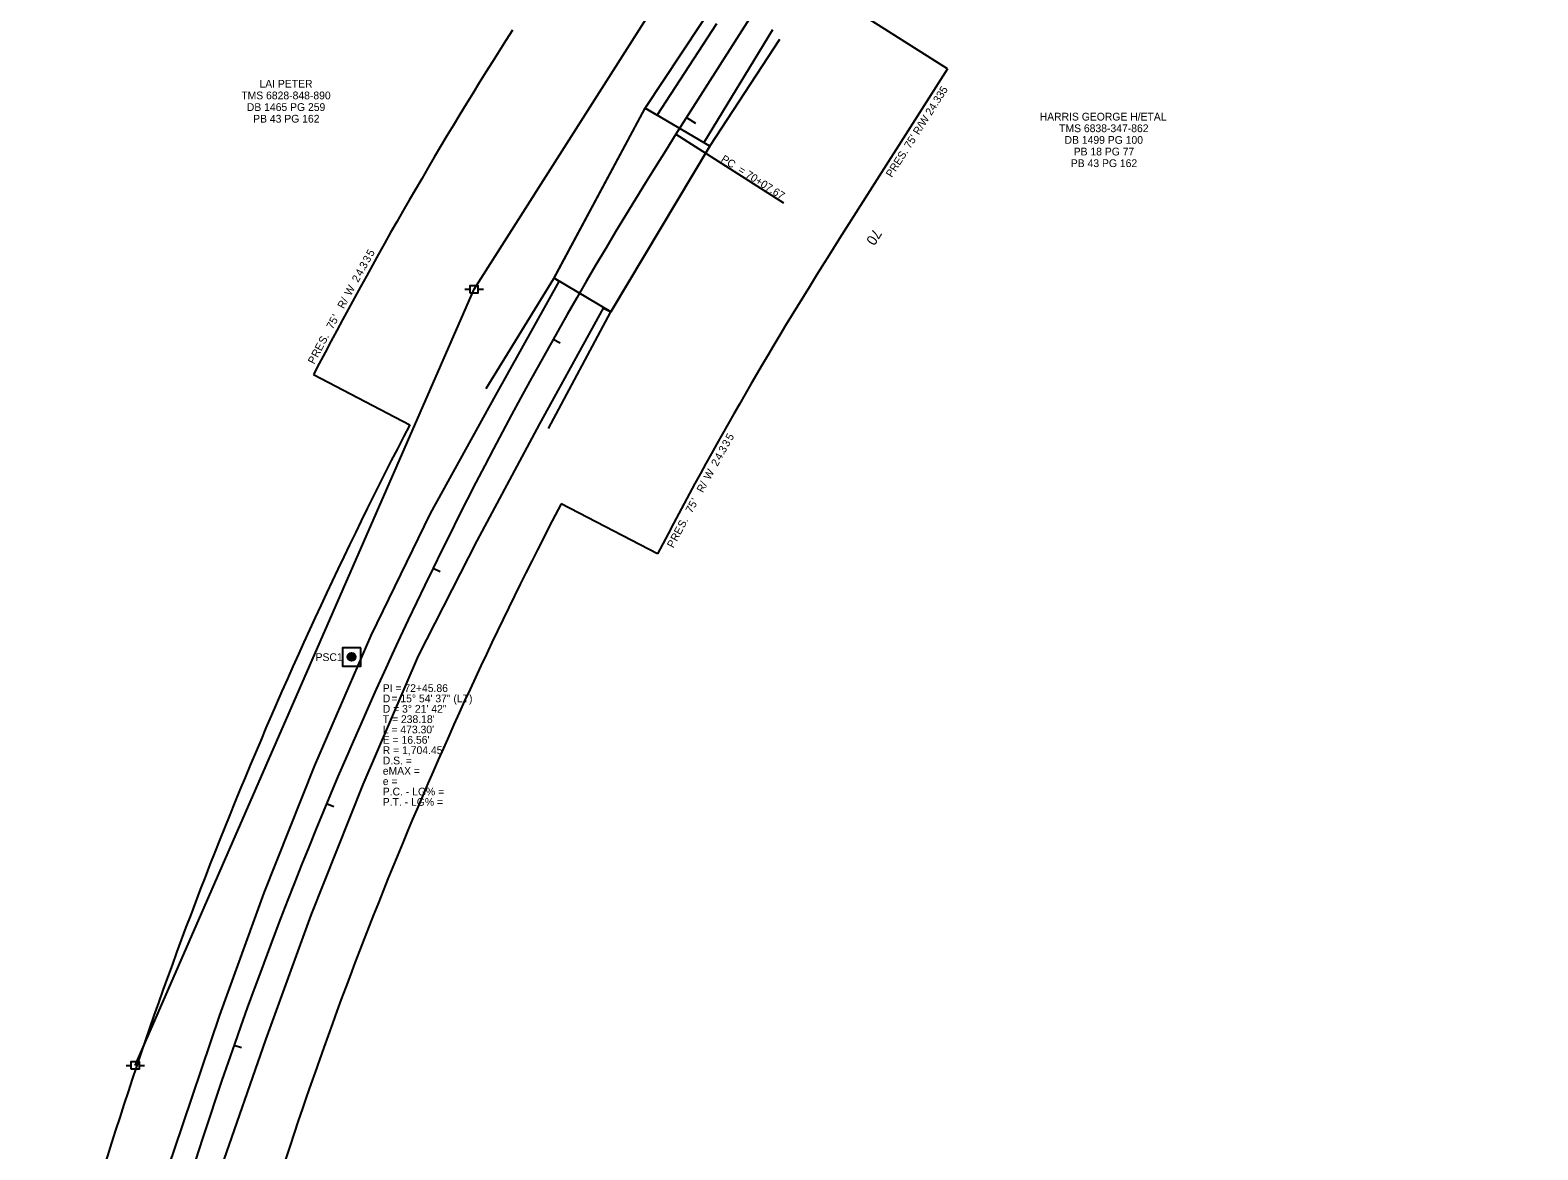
# Model space of a CAD drawing. Extents: x 1628604 to 1635417, y 886385 to 890338.
# Drawn here: x 1631062 to 1631645, y 888076 to 888509 of the extents above; entities that cross this region are included whole.
import ezdxf

# ---------------------------------------------------------------- set-up
doc = ezdxf.new("R2010")
doc.units = 0
for name, color, linetype in [('RD_EX_Bridge', 7, 'Continuous'), ('RD_EX_DV_TX_Prop', 7, 'Continuous'), ('RD_EX_GuardRail', 7, 'Continuous'), ('RD_EX_Road', 7, 'Continuous'), ('RD_EX_RW', 7, 'Continuous'), ('RD_EX_RW_TX', 7, 'Continuous'), ('RD_EX_SU_Pole', 7, 'Continuous'), ('RD_EX_UT', 7, 'Continuous'), ('RD_HC_Cl', 7, 'Continuous'), ('RD_HC_Data', 7, 'Continuous'), ('RD_HC_Data_Tic', 7, 'Continuous'), ('RD_HC_Survey', 7, 'Continuous'), ('RD_HC_Survey_txCode', 7, 'Continuous'), ('RD_HC_TX_Sta20', 7, 'Continuous'), ('SV_Plan_Bridge', 7, 'Continuous')]:
    doc.layers.add(name, color=color, linetype=linetype)

msp = doc.modelspace()

# ---------------------------------------------------------------- linework, layer by layer
at = {"layer": 'RD_EX_Bridge'}
for p, q in [((1631264.25, 888413), (1631299.43, 888478.7)), ((1631324.47, 888464.12), (1631299.43, 888478.7)), ((1631324.47, 888464.12), (1631286.15, 888399.98)), ((1631286.15, 888399.98), (1631264.25, 888413))]:
    msp.add_line(p, q, dxfattribs=at)
at = {"layer": 'RD_EX_GuardRail'}
for points in [[(1631237.99, 888370.31), (1631264.09, 888412.85), (1631299.43, 888478.7), (1631328.07, 888522.09)], [(1631262.14, 888354.83), (1631286.15, 888399.98), (1631324.47, 888464.12), (1631351.54, 888505.46)]]:
    msp.add_lwpolyline(points, dxfattribs=at)
at = {"layer": 'RD_EX_Road'}
for points in [[(1631061.65, 887886.91), (1631073.86, 887933.34), (1631087.39, 887979.64), (1631091.12, 887991.9), (1631101.62, 888029.8), (1631117.32, 888075.69), (1631134.95, 888128.02), (1631152.2, 888175.32), (1631171.74, 888224.62), (1631193.53, 888274.89), (1631216.42, 888321.99), (1631241.71, 888367.79), (1631266.25, 888411.67), (1631264.25, 888413), (1631299.43, 888478.7), (1631304.13, 888476.05), (1631327.2, 888511.47)], [(1631080.06, 887879.92), (1631092.71, 887925.82), (1631106.29, 887972.84), (1631120.8, 888022.75), (1631135.69, 888069.29), (1631152.84, 888118.51), (1631170.28, 888166.75), (1631190.48, 888217.25), (1631211.83, 888266.99), (1631234.52, 888311.47), (1631258.75, 888356.69), (1631283.38, 888401.46), (1631286.15, 888399.98), (1631324.47, 888464.12), (1631322.12, 888465.29), (1631348.79, 888509.12)]]:
    msp.add_lwpolyline(points, dxfattribs=at)
at = {"layer": 'RD_EX_RW'}
for p, q in [((1631416.35, 888493.91), (1631380.92, 888516.46)), ((1631416.35, 888493.91), (1631374.64, 888428.38)), ((1631171.2, 888375.72), (1631208.45, 888356.31)), ((1631304.22, 888306.41), (1631266.98, 888325.81))]:
    msp.add_line(p, q, dxfattribs=at)
for radius, start, end in [(1779.45, 147.5244, 152.47845), (1629.45, 147.5244, 152.47845), (1737.45, 152.47845, 163.43457), (1671.45, 152.47845, 163.43457)]:
    msp.add_arc((1632749.28, 887553.47), radius, start, end, dxfattribs=at)
at = {"layer": 'RD_EX_SU_Pole'}
for p, q in [((1631229.75, 888408.71), (1631231.81, 888408.71)), ((1631233.31, 888408.75), (1631233.31, 888408.75)), ((1631234.81, 888408.71), (1631236.95, 888408.71)), ((1631098.71, 888108.55), (1631100.77, 888108.55)), ((1631102.27, 888108.59), (1631102.27, 888108.59)), ((1631103.77, 888108.55), (1631105.91, 888108.55))]:
    msp.add_line(p, q, dxfattribs=at)
for points in [[(1631231.81, 888407.25), (1631231.81, 888410.25), (1631234.81, 888410.25), (1631234.81, 888407.25)], [(1631100.77, 888107.09), (1631100.77, 888110.09), (1631103.77, 888110.09), (1631103.77, 888107.09)]]:
    msp.add_lwpolyline(points, close=True, dxfattribs=at)
at = {"layer": 'RD_EX_UT'}
msp.add_lwpolyline([(1631102.27, 888108.59), (1631233.31, 888408.75), (1631462.97, 888769.93), (1631644.65, 888948.73)], dxfattribs=at)
at = {"layer": 'RD_HC_Cl'}
msp.add_line((1631589.45, 888905.57), (1631311.37, 888468.65), dxfattribs=at)
msp.add_arc((1632749.28, 887553.47), 1704.45, 147.5244, 163.43457, dxfattribs=at)
at = {"layer": 'RD_HC_Data'}
msp.add_line((1631311.37, 888468.65), (1631352.94, 888442.2), dxfattribs=at)
at = {"layer": 'RD_HC_Data_Tic'}
for p, q in [((1631315.49, 888475.13), (1631318.87, 888472.98)), ((1631263.93, 888389.46), (1631266.55, 888387.99)), ((1631217.47, 888300.93), (1631220.16, 888299.61)), ((1631176.28, 888209.82), (1631179.04, 888208.67)), ((1631140.5, 888116.46), (1631143.33, 888115.47))]:
    msp.add_line(p, q, dxfattribs=at)
at = {"layer": 'RD_HC_Survey'}
for p, q in [((1631184.45, 888266.22), (1631184.45, 888266.94)), ((1631184.5, 888266.05), (1631184.5, 888267.11)), ((1631184.55, 888265.93), (1631184.55, 888267.23)), ((1631184.6, 888265.83), (1631184.6, 888267.33)), ((1631184.65, 888265.75), (1631184.65, 888267.41)), ((1631184.7, 888265.67), (1631184.7, 888267.49)), ((1631184.75, 888265.61), (1631184.75, 888267.55)), ((1631184.8, 888265.55), (1631184.8, 888267.61)), ((1631184.85, 888265.49), (1631184.85, 888267.67)), ((1631184.9, 888265.44), (1631184.9, 888267.72)), ((1631184.95, 888265.4), (1631184.95, 888267.76)), ((1631185, 888265.36), (1631185, 888267.8)), ((1631185.05, 888265.32), (1631185.05, 888267.84)), ((1631185.1, 888265.29), (1631185.1, 888267.87)), ((1631185.15, 888265.25), (1631185.15, 888267.91)), ((1631185.2, 888265.22), (1631185.2, 888267.94)), ((1631185.25, 888265.2), (1631185.25, 888267.96)), ((1631185.3, 888265.17), (1631185.3, 888267.99)), ((1631185.35, 888265.15), (1631185.35, 888268.01)), ((1631185.4, 888265.13), (1631185.4, 888268.03)), ((1631185.45, 888265.11), (1631185.45, 888268.05)), ((1631185.5, 888265.1), (1631185.5, 888268.06)), ((1631185.55, 888265.08), (1631185.55, 888268.08)), ((1631185.6, 888265.07), (1631185.6, 888268.09)), ((1631185.65, 888265.06), (1631185.65, 888268.1)), ((1631185.7, 888265.05), (1631185.7, 888268.11)), ((1631185.75, 888265.04), (1631185.75, 888268.12)), ((1631185.8, 888265.03), (1631185.8, 888268.13)), ((1631185.85, 888265.03), (1631185.85, 888268.13)), ((1631185.9, 888265.03), (1631185.9, 888268.13)), ((1631185.95, 888265.03), (1631185.95, 888268.13)), ((1631186, 888265.03), (1631186, 888268.13)), ((1631186.05, 888265.03), (1631186.05, 888268.13)), ((1631186.1, 888265.03), (1631186.1, 888268.13)), ((1631186.15, 888265.04), (1631186.15, 888268.12)), ((1631186.2, 888265.04), (1631186.2, 888268.12)), ((1631186.25, 888265.05), (1631186.25, 888268.11)), ((1631186.3, 888265.06), (1631186.3, 888268.1)), ((1631186.35, 888265.07), (1631186.35, 888268.09)), ((1631186.4, 888265.09), (1631186.4, 888268.07)), ((1631186.45, 888265.1), (1631186.45, 888268.06)), ((1631186.5, 888265.12), (1631186.5, 888268.04)), ((1631186.55, 888265.14), (1631186.55, 888268.02)), ((1631186.6, 888265.16), (1631186.6, 888268)), ((1631186.65, 888265.19), (1631186.65, 888267.97)), ((1631186.7, 888265.21), (1631186.7, 888267.95)), ((1631186.75, 888265.24), (1631186.75, 888267.92)), ((1631186.8, 888265.27), (1631186.8, 888267.89)), ((1631186.85, 888265.3), (1631186.85, 888267.86)), ((1631186.9, 888265.34), (1631186.9, 888267.82)), ((1631186.95, 888265.38), (1631186.95, 888267.78)), ((1631187, 888265.42), (1631187, 888267.74)), ((1631187.05, 888265.47), (1631187.05, 888267.69)), ((1631187.1, 888265.52), (1631187.1, 888267.64)), ((1631187.15, 888265.58), (1631187.15, 888267.58)), ((1631187.2, 888265.64), (1631187.2, 888267.52)), ((1631187.25, 888265.71), (1631187.25, 888267.45)), ((1631187.3, 888265.79), (1631187.3, 888267.37)), ((1631187.35, 888265.88), (1631187.35, 888267.28)), ((1631187.4, 888265.99), (1631187.4, 888267.17)), ((1631187.45, 888266.13), (1631187.45, 888267.03)), ((1631187.5, 888266.35), (1631187.5, 888266.81))]:
    msp.add_line(p, q, dxfattribs=at)
msp.add_lwpolyline([(1631189.49, 888270.12), (1631182.42, 888270.12), (1631182.42, 888263.04), (1631189.49, 888263.04)], close=True, dxfattribs=at)
msp.add_circle((1631185.96, 888266.58), 1.55, dxfattribs=at)
at = {"layer": 'SV_Plan_Bridge'}
for points in [[(1631264.25, 888413), (1631299.43, 888478.7)], [(1631286.15, 888399.98), (1631324.47, 888464.12)]]:
    msp.add_lwpolyline(points, dxfattribs=at)

# ---------------------------------------------------------------- texts
at = {"layer": 'RD_EX_DV_TX_Prop'}
for s, p in [('LAI PETER', (1631150.32, 888486.68)), ('TMS 6828-848-890', (1631143.29, 888482.18)), ('DB 1465 PG 259', (1631145.44, 888477.68)), ('PB 43 PG 162', (1631147.88, 888473.18)), ('HARRIS GEORGE H/ETAL', (1631452.02, 888473.98)), ('TMS 6838-347-862', (1631459.54, 888469.48)), ('DB 1499 PG 100', (1631461.63, 888464.98)), ('PB 18 PG 77', (1631465.17, 888460.48)), ('PB 43 PG 162', (1631464.07, 888455.98))]:
    msp.add_text(s, height=3, dxfattribs=at).set_placement(p)
at = {"layer": 'RD_EX_RW_TX'}
for s, rotation, p in [("PRES. 75' R/W 24.335", 57.5244, (1631394.84, 888451.73)), ('5', 60.79723, (1631193.99, 888421.14)), ('4', 61.0769, (1631189.77, 888413.54)), ('3', 60.97354, (1631191.33, 888416.35)), ('3', 60.88539, (1631192.66, 888418.74)), ('.', 60.99938, (1631190.94, 888415.65)), ('W', 61.3558, (1631185.6, 888405.93)), ('2', 61.16353, (1631188.47, 888411.18)), ('/', 61.44547, (1631184.27, 888403.49)), ("'", 61.67118, (1631180.94, 888397.31)), ('R', 61.53819, (1631182.9, 888400.95)), ('7', 61.82773, (1631178.64, 888393.03)), ('5', 61.75478, (1631179.71, 888395.03)), ('E', 62.13399, (1631174.17, 888384.62)), ('S', 62.03824, (1631175.56, 888387.25)), ('.', 61.95009, (1631176.85, 888389.67)), ('P', 62.31942, (1631171.49, 888379.52)), ('R', 62.22671, (1631172.83, 888382.07)), ('5', 60.59835, (1631332.92, 888349.95)), ('3', 60.79123, (1631330.24, 888345.17)), ('3', 60.69479, (1631331.58, 888347.56)), ('2', 60.99908, (1631327.38, 888340.02)), ('4', 60.9043, (1631328.68, 888342.37)), ('.', 60.8195, (1631329.85, 888344.47)), ('W', 61.20942, (1631324.5, 888334.8)), ('R', 61.40895, (1631321.79, 888329.83)), ('/', 61.30752, (1631323.17, 888332.36)), ('7', 61.72571, (1631317.52, 888321.93)), ('5', 61.64589, (1631318.59, 888323.92)), ("'", 61.55444, (1631319.82, 888326.2)), ('S', 61.956, (1631314.44, 888316.16)), ('.', 61.85956, (1631315.73, 888318.58)), ('P', 62.26361, (1631310.37, 888308.45)), ('R', 62.16218, (1631311.71, 888311)), ('E', 62.06075, (1631313.05, 888313.54))]:
    msp.add_text(s, height=3, rotation=rotation, dxfattribs=at).set_placement(p)
at = {"layer": 'RD_HC_Data'}
msp.add_text('PC  = 70+07.67', height=3, rotation=327.5244, dxfattribs=at).set_placement((1631328.51, 888458.34))
for s, p in [('PI = 72+45.86', (1631198, 888253)), ('D', (1631198, 888249)), ('D = 3%%d 21\' 42"', (1631198, 888245)), ('   = 15%%d 54\' 37" (LT)', (1631198, 888249)), ("T = 238.18'", (1631198, 888241)), ("L = 473.30'", (1631198, 888237)), ("E = 16.56'", (1631198, 888233)), ("R = 1,704.45'", (1631198, 888229)), ('D.S. = ', (1631198, 888225)), ('eMAX = ', (1631198, 888221)), ('e = ', (1631198, 888217)), ('P.C. - LG% = ', (1631198, 888213)), ('P.T. - LG% = ', (1631198, 888209))]:
    msp.add_text(s, height=3, dxfattribs=at).set_placement(p)
at = {"layer": 'RD_HC_Survey_txCode'}
msp.add_text('PSC1', height=3, dxfattribs=at).set_placement((1631172.02, 888264.98))
at = {"layer": 'RD_HC_TX_Sta20'}
msp.add_text('70', height=4, rotation=237.5244, dxfattribs=at).set_placement((1631387.91, 888432.47))

doc.saveas('drawing.dxf')
